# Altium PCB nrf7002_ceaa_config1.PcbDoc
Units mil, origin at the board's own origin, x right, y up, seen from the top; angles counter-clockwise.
Board outline 582.35 x 436 mil, 4 copper layers (Top Layer, Mid-Layer 1, Mid-Layer 2, Bottom Layer), stack 37.194 mil thick; 22 components, 31 nets, 129 pads, 199 vias.
Unrouted connection lines stored in the file: 1.
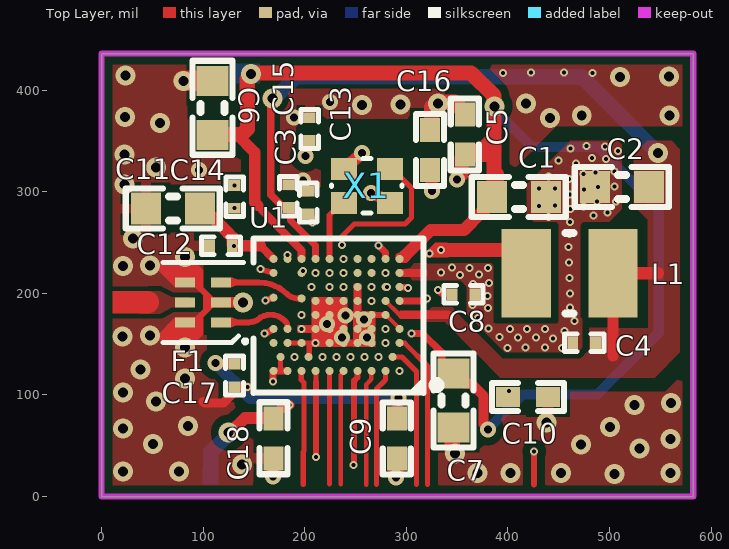
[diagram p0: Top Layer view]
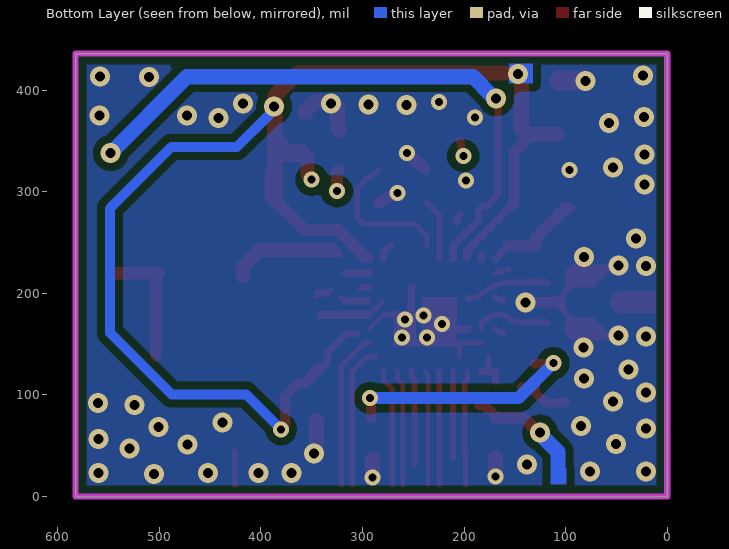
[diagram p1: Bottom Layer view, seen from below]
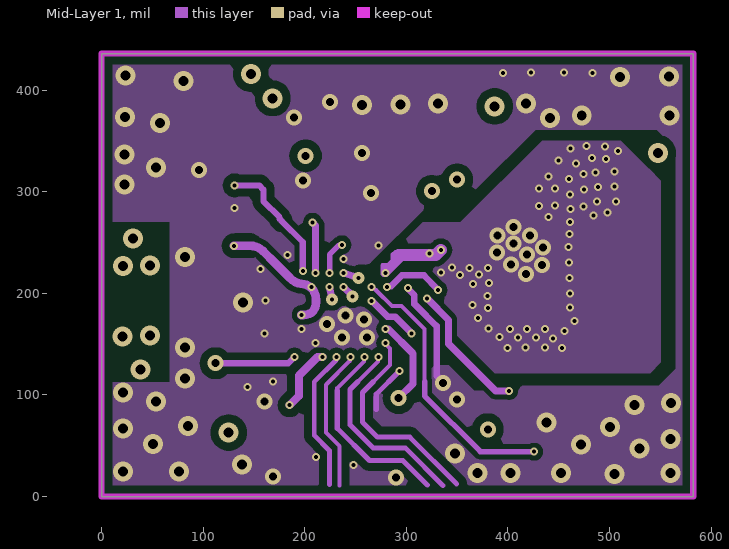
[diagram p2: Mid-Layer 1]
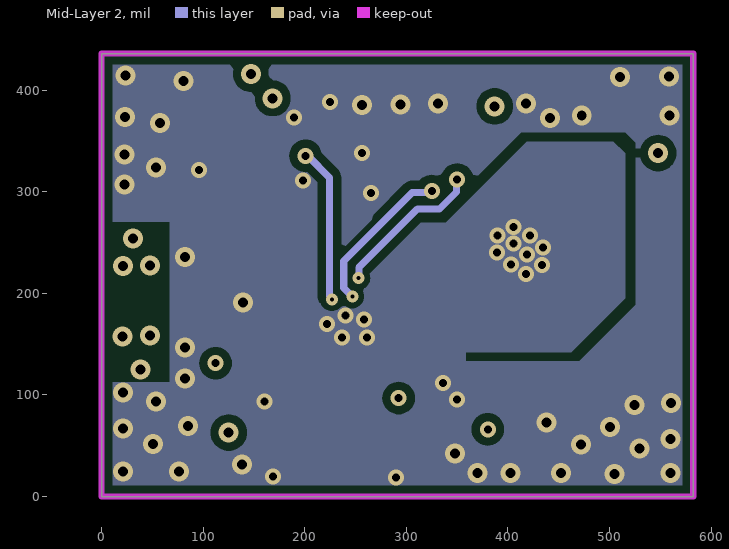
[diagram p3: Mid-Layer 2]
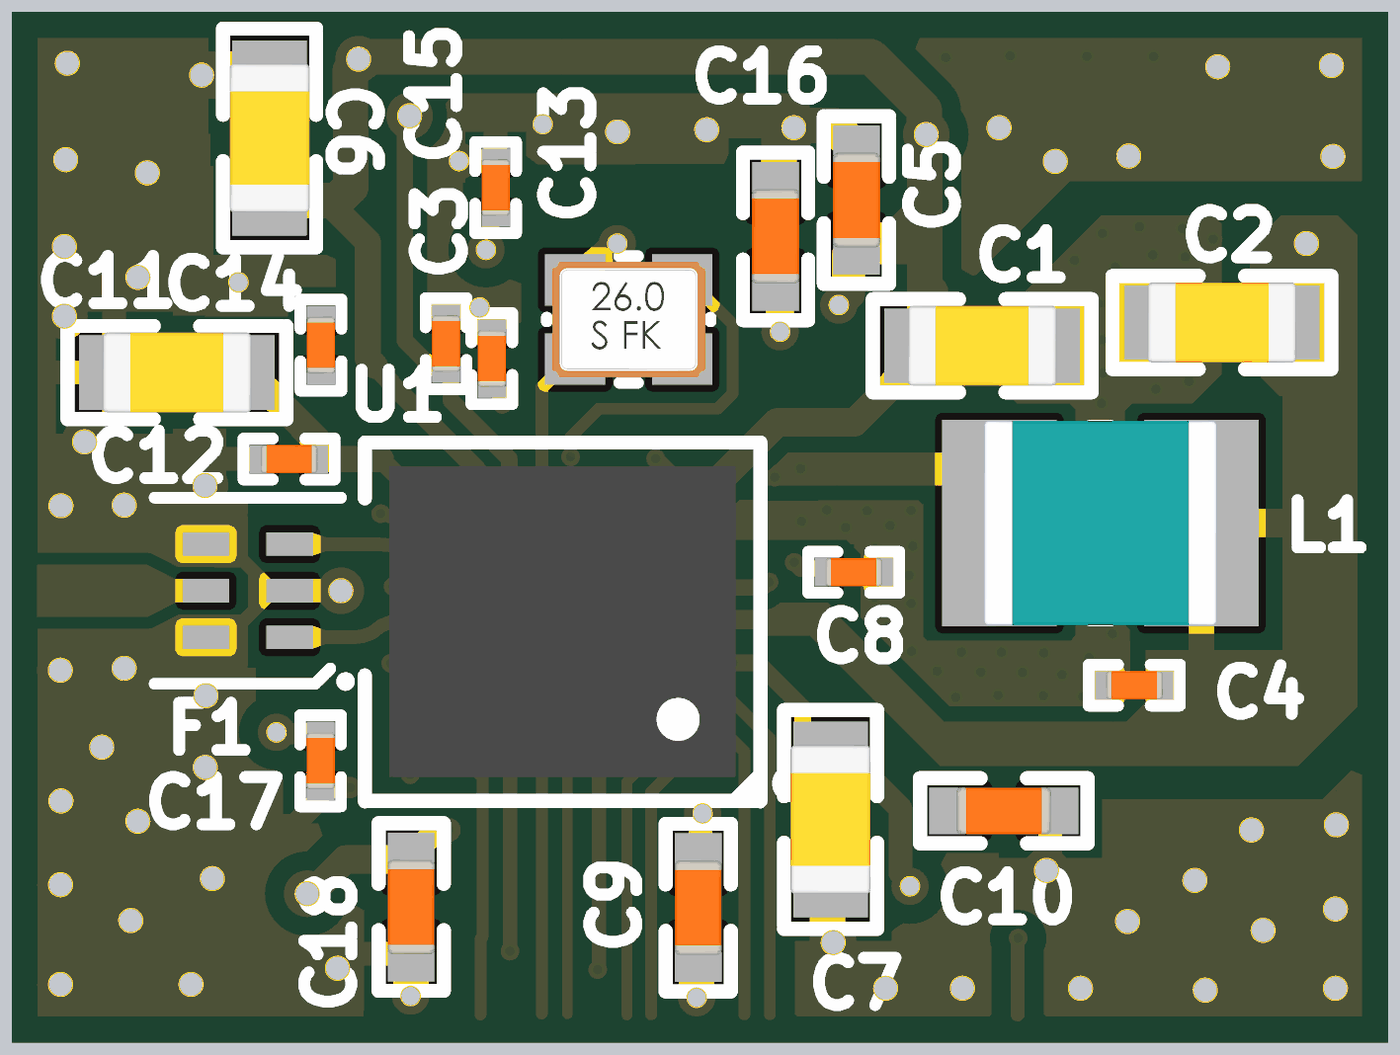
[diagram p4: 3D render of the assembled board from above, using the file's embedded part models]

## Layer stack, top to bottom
Top Solder: solder mask 1.063, Solder Resist, Dk 3.5
Top Layer: signal copper 0.709
Dielectric1: prepreg 3.5, FR-4, Dk 4.2
Mid-Layer 1: signal copper 1.378
Dielectric2: prepreg 26.02, FR-4, Dk 4.2
Mid-Layer 2: signal copper 1.378
Dielectric3: prepreg 3.5, FR-4, Dk 4.2
Bottom Layer: signal copper 0.709
Bottom Solder: solder mask 1.063, Solder Resist, Dk 3.5

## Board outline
0,0 0,436 582.35,436 582.35,0

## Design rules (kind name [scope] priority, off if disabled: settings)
Clearance Clearance_1 [InNet('RF_COM') vs InNet('GND')] p1: gap=4.76 ignorepadtopadclearanceinfootprint=TRUE except(5: Arc-Arc Arc-Track Arc-Fill Arc-Poly Arc-Region Track-Track Track-Fill Track-Poly Track-Region SMDPad-Fill SMDPad-Poly SMDPad-Region Fill-Fill Fill-Poly Fill-Region Poly-Poly Poly-Region Region-Region)
Clearance ANT_Clerance [InNamedPolygon('Top_Layer-GND') vs InNet('RF')] p2: gap=5 ignorepadtopadclearanceinfootprint=FALSE except(0: Arc-Hole Track-Hole SMDPad-Hole THPad-Hole Via-Hole Fill-Hole Poly-Hole Region-Hole Text-Hole)
Clearance Clearance_5 [InNet('BUCKEN') or InNet('DIGVDD') vs OnLayer('Mid-Layer 1')] p3: gap=5 ignorepadtopadclearanceinfootprint=FALSE
Clearance Clearance_2 [InNet('VDD_BUCK') vs OnLayer('Top Layer')] p4: gap=6 ignorepadtopadclearanceinfootprint=FALSE except(3.7: Arc-SMDPad Track-SMDPad; 5: Arc-Arc Arc-Track Track-Track; 5.5: SMDPad-SMDPad)
Clearance Clearance_bga [WithinRoom('bga')] p5: gap=5.5 ignorepadtopadclearanceinfootprint=FALSE except(4: Arc-Arc Arc-Track Arc-SMDPad Arc-THPad Arc-Via Track-Track Track-SMDPad Track-THPad Track-Via SMDPad-SMDPad SMDPad-THPad SMDPad-Via THPad-THPad THPad-Via Via-Via; 4.3: Arc-Text Track-Text SMDPad-Text THPad-Text Via-Text Fill-Text Poly-Text Region-Text Text-Text; 5: Arc-Hole Track-Hole SMDPad-Hole THPad-Hole Via-Hole Fill-Hole Poly-Hole Region-Hole Text-Hole)
Clearance Clearacnce_microvia [AsMM(ViaDiameter) = 0.3 vs AsMM(ViaDiameter) = 0.3] p6: gap=3.94 ignorepadtopadclearanceinfootprint=FALSE
Clearance Polygon_Clearance [(InNamedPolygon('Top_Layer-GND')) or (InNamedPolygon('Bottom_Layer-GND')) or (InNamedPolygon('Mid_Layer_1-GND')) or (InNamedPolygon('Mid_Layer_4-GND'))] p7: gap=8 ignorepadtopadclearanceinfootprint=FALSE except(0: Arc-Hole Track-Hole SMDPad-Hole THPad-Hole Via-Hole Fill-Hole Poly-Hole Region-Hole Text-Hole)
Clearance [All] p8: gap=6 ignorepadtopadclearanceinfootprint=FALSE except(0: Arc-Hole Track-Hole SMDPad-Hole THPad-Hole Via-Hole Fill-Hole Poly-Hole Region-Hole Text-Hole; 5.5: Arc-Arc Arc-Track Track-Track SMDPad-Region; 5.7: THPad-Via)
ComponentClearance [All] p1 off: gap=10 collisioncheckmode=3 verticalgap=10 showdistances=FALSE
DiffPairsRouting [All] p1: maxlimit=8 minlimit=3 mostfreqgap=7.5 toplayer_mingap=5 toplayer_minwidth=4.3 toplayer_maxwidth=4.5 toplayer_prefwidth=4.3 midlayer1_maxgap=4 midlayer1_prefgap=3.5 midlayer1_minwidth=4.3 midlayer1_maxwidth=5 midlayer1_prefwidth=4.3 midlayer4_maxgap=4 midlayer4_prefgap=3.5 midlayer4_minwidth=4.3 midlayer4_maxwidth=5 midlayer4_prefwidth=4.3 bottomlayer_mingap=5 bottomlayer_minwidth=4.3 bottomlayer_maxwidth=4.5 bottomlayer_prefwidth=4.3 maxuncoupledlength=500
FabricationTestPointUsage TestPointUsage [All] p1: valid=0 allowmultiple=FALSE
FabricationTestpoint Testpoint [All] p1: side=3 testpointundercomponent=TRUE minsize=40 maxsize=100 preferedsize=60 minholesize=0 maxholesize=40 preferedholesize=32 testpointgrid=1 allowsidetop=TRUE allowsidebottom=TRUE usegrid=TRUE gridtolerance=0.01
Height [All] p1 off: minheight=0 maxheight=1000 prefheight=500
HoleSize [All] p1: absolutevalues=TRUE maxlimit=300 minlimit=3.94 maxpercent=80.000 minpercent=20.000
HoleToHoleClearance [All] p1: gap=7 allowstackedmicrovias=TRUE
MinimumAnnularRing [All] p1 off: minimumring=6
PolygonConnect PolygonConnect_1 [isVia and innet(gnd) or InComponent('J5_not for this board')] p1: connectstyle=Direct reliefconductorwidth=10 reliefentries=4 polygonreliefangle="90 Angle" airgapwidth=10
PolygonConnect [All] p2: connectstyle=Relief reliefconductorwidth=10 reliefentries=4 polygonreliefangle="90 Angle" airgapwidth=10
RoomDefinition bga [False vs False] p1: confinementstyle=ConfineIn formatcopy=TRUE lockcomponents=FALSE outline 136.29,271.2 341.54,271.2 341.54,113.29 136.29,113.29
RoutingVias [All] p1: holewidth=12.01 width=24 viastyle="Through Hole" minholewidth=3.94 minwidth=11.81 maxholewidth=12.01 maxwidth=24.02 useviatemplates=TRUE viatemplateguid#1={ABC4FB01-9861-4EA0-89FF-0108A0A2DD33} viatemplateguid#2={9F61FF23-C90F-4B7F-A7DC-5F6911D9F630} viatemplateguid#3={EDF5FEF7-A820-4EA2-9A2F-3AF23343353B} viatemplateguid#4={9A17AC30-7ABC-4A8B-B742-8CA8D66FB78C} viatemplateguid#5={FF87C72B-F86E-4E3E-89CE-017383A4E30D} viatemplatename#1=v20h10m0 viatemplatename#2=v40h20m0mx0 viatemplatename#3=v50h25m0mx0 viatemplatename#4=v50h25m0mx0_2670034071 viatemplatename#5=v30h10
SilkToSolderMaskClearance SilkscreenOverComponentPads [IsPad] p1: minsilkscreentomaskgap=10 clearancetoexposedcopper=TRUE
SolderMaskExpansion [IsVia] p1: expansion=3 istentingtop=TRUE
SolderMaskExpansion SolderMaskExpansion_1 [All] p2: expansion=3 istentingtop=FALSE
SupplyNets "Schematic Supply Nets_5" [InNet('GND')] p1: voltage=0.000
SupplyNets "Schematic Supply Nets_4" [InNet('PWRIOVDD')] p2: voltage=0.000
SupplyNets "Schematic Supply Nets_3" [InNet('VDDIO')] p3: voltage=0.000
SupplyNets "Schematic Supply Nets_2" [InNet('VDD_BUCK')] p4: voltage=0.000
SupplyNets "Schematic Supply Nets_1" [InNet('PALDO')] p5: voltage=0.000
SupplyNets "Schematic Supply Nets" [InNet('VBAT')] p6: voltage=0.000
UnRoutedNet [All] p1: checkbadconnections=TRUE
Width [All] p1: maxlimit=50 minlimit=4 preferedwidth=6
21 further rules are at their usual default settings.

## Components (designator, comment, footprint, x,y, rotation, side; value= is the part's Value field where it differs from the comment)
C1 "4.7µF" CAPC1608X06L 410.63,294.77 r180 top
C2 "4.7µF" CAPC1608X06L 512,304.6 r0 top
C3 "0.22µF" CAPC0603X03L_C 183.88,295.65 r270 top
C4 "0.47µF" CAPC0603X03L_C 474.97,151.19 r0 top
C5 "1.0µF" CAPC1005X04L 357.46,356.4 r270 top
C6 "4.7µF" CAPC1608X06L 109.25,382.66 r270 top
C7 "2.2µF" CAPC1608X06L 346.51,94.38 r90 top
C8 "10nF" CAPC0603X03L_C 356.32,198.96 r180 top
C9 "2.2µF" CAPC1005X04L 290.53,57.09 r90 top
C10 "1.0µF" CAPC1005X04L 419.76,98.05 r0 top
C11 "4.7µF" CAPC1608X06L 70.08,283.43 r0 top
C12 "100nF" CAPC0603X03L_C 117.47,246.85 r0 top
C13 "22nF" CAPC0603X03L_C 203.26,289.32 r270 top
C14 "0.47µF" CAPC0603X03L_C 130.98,295.06 r90 top
C15 "2.2µF" CAPC0603X03L_C 204.85,361.7 r270 top
C16 "1.0µF" CAPC1005X04L 323.26,341.03 r270 top
C17 "100nF" CAPC0603X03L_C 130.79,119.2 r90 top
C18 "2.2µF" CAPC1005X04L 169.14,57.37 r90 top
F1 "LFD_5G_Diplexer" CAF-50P160X80-6N 100.03,191.15 r180 top value=LFD182G45DCHD277
L1 "3.3µH" INDC2520X10N 460.62,219.77 r0 top
U1 "nRF7002-CEAA" nRF7002_WLCSP_R2 233.2,179.61 r180 top
X1 "40MHz" BT-XTAL_1612 261.11,305.87 r0 top locked

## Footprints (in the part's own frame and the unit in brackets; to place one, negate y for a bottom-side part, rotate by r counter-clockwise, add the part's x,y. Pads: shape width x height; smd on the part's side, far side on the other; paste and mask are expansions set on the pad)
BT-XTAL_1612 [mm] "Crystal 1.6 x 1.2 mm"
  rect 0.65x0.55 smd: 1(-0.575,-0.425) 2(0.575,-0.425) 3(0.575,0.425) 4(-0.575,0.425)
  silkscreen extent -0.88,-0.68 0.88,0.68, body extent -0.83,-0.63 0.83,0.63, height 0.41
CAF-50P160X80-6N [mm] "Chip Array, Flat, 6-Leads, Pitch 0,50mm,  Body 1,60x0,80mm,  IPC Medium Density"
  rect 0.5x0.25 smd mask+0.08: 1(-0.45,0.5) 2(-0.45,0) 3(-0.45,-0.5) 5(0.45,-0.5) 6(0.45,0) 7(0.45,0.5)
  Top Layer region: 0.693,0.375 0.2,0.375 0,0.175 0,-0.175 0.2,-0.375 0.699,-0.375 1.175,-0.852 1.175,-0.95 0.15,-0.95 0,-0.8 0,-0.375 -0.25,-0.125 -0.8,-0.125 -0.9,-0.225 -1,-0.225 -1,0.225 -0.9,0.225 -0.8,0.125 -0.25,0.125 0,0.375 0,0.8 0.15,0.95 1.175,0.95 1.175,0.857
  silkscreen extent -1.1,-1 1,1.02, body extent -0.5,-0.88 0.5,0.88, height 0.67
CAPC0603X03L_C [mm] "Chip Capacitor, 2-Leads, Body 0.6x0.3mm, IPC High Density"
  rect 0.27x0.3 smd mask+0.05: 1(-0.285,0) 2(0.285,0)
  silkscreen extent -0.49,-0.22 0.49,0.22, body extent -0.3,-0.15 0.31,0.15, height 0.3
CAPC1005X04L [mm] "Chip Capacitor, 2-Leads, Body 1.0x0.5mm, IPC High Density"
  rect 0.6x0.5 smd: 1(-0.5,0) 2(0.5,0)
  silkscreen extent -0.9,-0.35 0.9,0.35, body extent -0.51,-0.25 0.51,0.25, height 0.5
CAPC1608X06L [mm] "Chip Capacitor, 2-Leads, Body 1.6x0.8mm, IPC High Density"
  rect 0.75x0.8 smd: 1(-0.675,0) 2(0.675,0)
  silkscreen extent -1.17,-0.5 1.17,0.5, body extent -0.8,-0.43 0.8,0.43, height 0.8
INDC2520X10N [mm] "Chip Inductor, 2-Leads, Body 2,50x2,00mm, IPC Medium Density"
  rect 1.23x2.22 smd: 1(-1.085,0) 2(1.085,0)
  silkscreen extent -0.1,-1.01 0.1,1.01, body extent -1.25,-1.1 1.25,1.1, height 1.98
nRF7002_WLCSP_R2 [mm] "BGA, 90-Leads, Body 3.72x3.34mmx0.54mm, Pitch 0.34mm"
  round 0.2 smd mask-0.01: A1(-1.526,1.422) A3(-1.176,1.422) A5(-0.826,1.422) A7(-0.476,1.422) A9(-0.126,1.422) A11(0.224,1.422) A13(0.574,1.422) A16(0.924,1.422) A18(1.274,1.422) A20(1.624,1.422) B2(-1.352,1.072) B4(-1.002,1.072) B6(-0.652,1.072) B8(-0.302,1.072) B10(0.049,1.072) B12(0.399,1.072) B15(0.749,1.072) B17(1.099,1.072) B19(1.449,1.072) C1(-1.526,0.722) C3(-1.176,0.722) C5(-0.826,0.722) C7(-0.476,0.722) C9(-0.126,0.722) C11(0.224,0.722) C13(0.574,0.722) C16(0.924,0.722) C18(1.274,0.722) C20(1.624,0.722) D1(-1.526,0.372) D3(-1.176,0.372) D5(-0.826,0.372) D7(-0.476,0.372) D9(-0.126,0.372) D11(0.224,0.372) D13(0.574,0.372) D16(0.924,0.372) D18(1.274,0.372) D20(1.624,0.372) E3(-1.176,0.022) E5(-0.826,0.022) E7(-0.476,0.022) E9(-0.126,0.022) E11(0.224,0.022) E13(0.574,0.022) E16(0.924,0.022) F1(-1.526,-0.328) F3(-1.176,-0.328) F5(-0.826,-0.328) F7(-0.476,-0.328) F9(-0.126,-0.328) F11(0.224,-0.328) F13(0.574,-0.328) G16(0.924,-0.391) H20(1.624,-0.411) J1(-1.526,-0.679) J3(-1.176,-0.679) J5(-0.826,-0.679) J7(-0.476,-0.679) J9(-0.126,-0.679) J11(0.224,-0.679) J14(0.677,-0.679) K1(-1.526,-1.029) K3(-1.176,-1.029) K5(-0.826,-1.029) K7(-0.476,-1.029) K9(-0.126,-1.029) K11(0.224,-1.029) K13(0.574,-1.029) K16(0.924,-1.029) K20(1.624,-1.029) L1(-1.526,-1.379) L3(-1.176,-1.379) L5(-0.826,-1.379) L7(-0.476,-1.379) L9(-0.126,-1.379) L11(0.224,-1.379) L13(0.574,-1.379) L16(0.924,-1.379) L18(1.274,-1.379) L20(1.624,-1.379)
  silkscreen extent -2.53,-1.89 2.13,1.97, body extent -1.86,-1.63 1.86,1.71, height 0.54

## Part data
C1 C2 C6 C11: library part C0603-4µ7-25V-X6S-GRM188C81E475KE11, "Capacitor, Ceramic, X6S 0603,±10%, 25V", Manufacturer=Murata, Manufacturer Part Number=GRM188C81E475KE11D, Supplier Part Number 1=490-7199-1-ND
C3: library part C0201-220n-10V-X5R-GRM033R61A224KE90, "Capacitor, Ceramic, X5R 0201, ±10%, 10V", Manufacturer=Murata, Manufacturer Part Number=GRM033R61A224KE90D, Supplier Part Number 1=81-GRM33R61A224KE90D
C4 C14: library part C0201-470n-6.3V-X5R-GRM033R60J474KE90, "Capacitor, Ceramic, X5R 0201,±10%, 6.3V", Manufacturer=Murata, Manufacturer Part Number=GRM033R60J474KE90D, Supplier Part Number 1=490-10409-1-ND
C5: library part C0402-1µ0-35V-X5R-GRM155R6YA105KE11, "Capacitor, Ceramic, X5R 0402,±10%, 35V", Manufacturer=Murata, Manufacturer Part Number=GRM155R6YA105KE11D, Supplier Part Number 1=81-GRM155R6YA105KE1D
C7: library part C0603-2µ2-16V-X7S-GRM188C71C225KE11, "Capacitor, Ceramic, X7S 0603,±10%,16V", Manufacturer=Murata, Manufacturer Part Number=GRM188C71C225KE11D, Supplier Part Number 1=81-GRM188C71C225KE1D
C8: library part C0201-10n-16V-X7R-GRM033R71C103KE14, "Capacitor, Ceramic, X7R 0201,±10%, 16V", Manufacturer=Murata, Manufacturer Part Number=GRM033R71C103KE14D, Supplier Part Number 1=490-14453-1-ND
C9 C18: library part C0402-2µ2-25V-X5R-GRM155R61E225KE11, "Capacitor, Ceramic, X5R 0402,±10%, 25V", Manufacturer=Murata, Manufacturer Part Number=GRM155R61E225KE11D, Supplier Part Number 1=81-GRM155R61E225KE1D
C10: library part C0402-1µ0-16V-X6S-GRM155C81C105KE11J, "Capacitor, Ceramic, X6S 0402,±10%, 16V", Manufacturer=Murata, Manufacturer Part Number=GRM155C81C105KE11J, Supplier Part Number 1=81-GRM155C81C105KE1J
C12 C17: library part C0201-100n-16V-X7S-GRM033C71C104KE14, "Capacitor, Ceramic, X7S 0201,±10%, 16V", Manufacturer=Murata, Manufacturer Part Number=GRM033C71C104KE14D, Supplier Part Number 1=81-GRM33C71C104KE14D
C13: library part C0201-22n-10V-X5R-GRM033R61A223KE84, "Capacitor, Ceramic, X5R 0201,±10%, 10V", Manufacturer=Murata, Manufacturer Part Number=GRM033R61A223KE84D, Supplier Part Number 1=81-GRM033R61A223KE4E
C15: library part C0201-2µ2-10V-X5R-GRM033R61A225KE47, "Capacitor, Ceramic, X5R 0201,±10%, 10V", Manufacturer=Murata, Manufacturer Part Number=GRM033R61A225KE47D, Supplier Part Number 1=81-GRM033R61A225KE7D
C16: library part C0402-1µ0-10V-X7S-GRM155C71A105KE11, "Capacitor, Ceramic, X7S 0402,±10%,10V", Manufacturer=Murata, Manufacturer Part Number=GRM155C71A105KE11D, Supplier Part Number 1=81-GRM155C71A105KE1J
F1: library part LFD182G45DCHD277, "Signal Conditioning 2.4GHz and 5GHz Diplexer", Manufacturer=Murata, Supplier Part Number 1=81-LFD182G45DCHD277
L1: library part L1008-3µ3-LQM2HPN3R3MGCL, "Inductor, 1A, ±20%, 200mOhm", Manufacturer=Murata, Manufacturer Part Number=LQM2HPN3R3MGCL, Supplier Part Number 1=490-12070-1-ND
U1: "Wi-Fi Dual Band Companion chip WLCSP", Manufacturer="Nordic Semiconductor"
X1: library part XTAL_SMD1612_40MHz_8p_40_85, "XTAL SMD 1612, 40MHz, Cl=8pF, Total Tol: ±10ppm, -40-85C", Manufacturer="Abracon Corporation", Manufacturer Part Number=ABM12W-40.0000MHZ-8-D1X-T3, Supplier Part Number 1=535-13992-1-ND

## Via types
v1: diameter 7.87, hole 3.94, Top Layer to Mid-Layer 1, tented top, 73 vias
v2: diameter 19.68, hole 9.84, Top Layer to Bottom Layer, tented both sides, 52 vias
v3: diameter 7.87, hole 3.94, Top Layer to Mid-Layer 1, tented both sides, 39 vias
v4: diameter 15.75, hole 7.87, Top Layer to Bottom Layer, tented both sides, 19 vias
v5: diameter 15.75, hole 7.87, Mid-Layer 1 to Mid-Layer 2, tented both sides, 13 vias
v6: diameter 11.81, hole 3.94, Mid-Layer 1 to Mid-Layer 2, tented both sides, 3 vias

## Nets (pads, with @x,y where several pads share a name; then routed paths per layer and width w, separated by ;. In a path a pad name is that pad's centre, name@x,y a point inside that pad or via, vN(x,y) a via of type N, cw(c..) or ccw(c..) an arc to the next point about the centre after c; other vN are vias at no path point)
AFELDO: C16.2 U1.J9 | length 185.2
  Top Layer w12: C16.2 325,319.61 325,300.83 v4(325.14,300.69)
  Mid-Layer 1 w7: v3(238.16,206.33) v6@246.73,197.75
  Mid-Layer 2 w7: v6(246.73,196.85) 238.39,205.19 238.39,231.78 277.81,271.2 305.82,299.21 321.66,299.21 v4@323.14,300.69
BUCKEN: U1.J5 | length 298.1
  Top Layer w6: 425.63,12 425.63,44.02 v1(425.83,44.21)
  Mid-Layer 1 w4: v3(265.73,206.33) 266.77,206.33 270.06,203.04 270.35,203.04 285.88,187.51 295.34,187.51 317.91,164.94 317.91,113.29
  Mid-Layer 1 w5.5: 317.91,113.29 317.91,99.14 372.83,44.21 v1(425.83,44.21)
BUCKOUT: L1.1 U1.K3 | length 143.5
  Top Layer w14: v3(333.9,242.73) 401.19,242.73 417.91,226.02 L1.1@417.91,216.77
  Mid-Layer 1 w12: 292.58,237.83 329,237.83 v3(333.9,242.73)
  other v3: 279.56,220.11 322.89,239.15
BUCKVMID: C8.2 U1.J3 | length 74
  Top Layer w7: v1@331.93,202.56 334.07,200.42 341.54,200.42 343.64,200.42 C8.2@344.91,199.15
  Mid-Layer 1 w6.5: v3@281.68,206.61 281.77,206.61 282.2,207.04 284.83,207.04 295.64,217.85 317.56,217.85 ; 317.56,217.29 330.45,204.4 330.9,203.97 v1@331.14,203.97
  other v1: 331.14,203.15
  other v3: 281.14,206.35
COEX_REQ: U1.A5 | length 114.2
  Top Layer w4.5: 260.39,11.68 260.39,110.31 263.37,113.29 265.56,115.47 265.56,123.46 U1.A5
DIGVDD: C10.1 U1.F1 | length 158.9
  Top Layer w7: U1.F1@294.66,192.54 317.95,192.54 320.26,194.86 v3(320.5,194.86)
  Mid-Layer 1 w7: v3(320.5,194.86) 341.54,173.81 341.54,150.38 387.96,103.96 v1(401.19,103.96)
GND: C1.1 C2.1 C3.1 C4.1 C5.1 C6.1 C7.1 C8.1 C9.1 C10.2 C11.1 C12.1 C13.1 C14.1 C15.1 C16.1 C17.1 C18.1 F1.2 F1.5 F1.7 U1.A1 U1.A7 U1.A13 U1.A18 U1.A20 U1.B15 U1.B19 U1.C5 U1.C7 U1.C9 U1.C11 U1.C13 U1.C16 U1.C18 U1.D1 U1.D5 U1.D7 U1.D9 U1.D11 U1.D13 U1.D16 U1.D20 U1.E3 U1.E5 U1.E7 U1.E9 U1.E11 U1.E13 U1.F7 U1.F9 U1.F11 U1.F13 U1.H20 U1.J1 U1.J7 U1.K1 U1.K20 U1.L3 U1.L9 U1.L18 X1.2 X1.4 | length 804.1
  Top Layer w4: U1.L18 U1.L18@183.09,233.96 ; v3(183.15,237.95) v3(183.15,237.95) ; U1.E3 279.78,178.76 293.29,165.25 U1.D1
  Top Layer w5: 175.94,123.63 175.94,137.2 U1.B19 ; U1.C18 U1.C16 204.44,151.19 ; U1.B15@204.44,138.13 204.44,151.19 ; v3(210.59,151.19) 204.44,151.19 ; 210.92,113.29 U1.A13@210.92,123.3
  Top Layer w5.9: v3(156.25,223.75) U1.K20
  Top Layer w6: v2(139.4,191.15) v2@140.17,190.38 ; v1(210.92,38.71) 210.92,113.29 ; v1@248.61,30.88 248.61,114.11 251.89,117.39 251.89,123.57 U1.A7 ; U1.E5 U1.E3@278.27,178.76 ; 316.9,220.11 317.41,220.61
  Top Layer w6.5: U1.C9 U1.C7 ; U1.J1 293.56,206.06 299.9,206.06 301.42,204.54 v3@301.79,204.54
  Top Layer w6.8: v3@161.48,160.43 U1.D20 ; v3(161.48,193.03) U1.H20
  Top Layer w7: v3(168.72,113.29) 168.89,113.46 168.89,123.03 169.34,123.49 169.34,123.63 175.94,123.63 U1.A18 ; U1.L18@183.09,233.96 v3(183.15,237.95) ; U1.E7@251.53,178.35 U1.E7 ; v3(272.52,247.08) 279.4,240.2 279.4,234.24 U1.L3@279.51,234.13
  Top Layer w7.87: U1.K1 316.9,220.11
  Top Layer w8: v4(239.97,178.35) U1.E7@251.53,178.35
  Top Layer w9: 100.03,93.63 101.52,92.14 119.77,92.14 129.89,102.25 129.89,107.66 130.13,107.91 v3(143.39,107.91)
  Top Layer w12: X1.4 v4(256.27,337.96) ; v4@265.28,299.88 X1.2
  Top Layer w15: v4(168.89,19.68) 169.01,19.8 169.01,38.13 C18.1@169.2,38.33 ; v4(289.88,19) C9.1@289.88,37.14 ; C16.1 324.63,362.08 v2@324.63,383.15 ; v2@330.86,386.13 332.12,386.13 334.02,388.03 347.5,388.03 356.32,379.2 C5.1@356.32,377.23 ; C7.1@344.84,74.73 345.24,74.34 345.24,43.07 v2@345.97,42.34
  Top Layer w20: v2(80.51,409.23) C6.1@106.25,409.23
  Mid-Layer 1 w5: 270.35,85.85 270.35,100.68 v3(293.29,123.63)
  Mid-Layer 1 w6.5: v3@301.79,204.54 301.79,204.17 307.88,198.09 307.88,189.47 310.3,187.04 329.15,168.2 329.71,168.2 329.71,119.2 334.8,114.11 v5@334.8,111.61
  other v1: 248.02,30.88 399.37,146.09 453.19,146.39 417.36,146.88 436.5,146.74 444.34,155.68 410,156.7 427.7,156.57 391.59,157.1 455.88,162.85 380.71,165.54 401.84,165.16 418.79,165.16 436.65,164.81 465.68,172.92 370.26,175.81 380.54,185.79 461.02,185.98 365.06,188.31 379.68,197.62 461.13,199.75 365.33,209.11 381.32,210.05 460.59,215.29 352.91,217.88 371.63,218.78 334.24,220.61 344.84,225.32 361.96,225.01 380.54,225.19 459.93,230.56 459.7,245.59 460.59,258.41 461.13,270.44 439.78,275.39 484.09,276.46 498.02,279.67 461.6,283.19 430.66,285.81 446.12,286.64 474.25,285.72 487.55,290.46 506.09,290.35 461.13,297.29 474.97,302.15 430.66,303.38 446.12,303 488.75,304.89 504.96,305.09 459.9,312.6 439.86,315.07 474.47,317.53 486.19,319.06 504.96,319.81 466.96,328.05 449.6,330.93 496.48,332.37 482.69,333.15 508.28,339.88 461.5,342.37 495.28,344.37 477.1,345.12 395.2,416.69 422.44,417.4 454.93,417.2 483.1,417.09
  other v2: 504.96,22.2 369.8,22.99 402.29,22.99 452.2,22.99 559.98,22.99 20.85,24.64 76,24.64 137.98,31.46 347.62,42.34 529.43,47.51 50.55,51.65 472.11,51.25 559.98,56.53 20.85,66.8 500.56,68.63 85.04,69.38 437.82,72.84 524.49,89.95 560.39,92.14 53.55,93.63 21,102.21 82.05,116.44 38.28,124.99 82.34,146.74 20.76,157.54 47.76,158.35 21,227.1 47.76,227.35 81.94,235.66 31,254.12 22.49,307.27 53.55,323.69 22.49,336.72 57.55,367.92 23.02,373.48 441.53,372.75 472.61,375 558.96,374.86 256.46,385.23 294.14,386.13 330.98,387 417.76,387 510.25,412.77 558.3,413.27 23.72,414.27
  other v3: 160.47,160.43 196.81,164.98 301.79,205.31 238.04,233.89 130.98,283.84
  other v4: 236.45,156.68 261.08,156.57 221.94,169.94 258.29,174.4 265.26,298.85 198.04,310.93 96.09,321.6 189.36,372.92 224.79,388.49
  other v5: 160.36,93.77 349.61,95.35 335.8,111.61 417.79,219.07 433.64,227.72 403.04,228.64 418.69,238.32 389.29,240.03 434.64,245.07 405.43,249.02 389.58,257.04 421.44,256.9 405.43,265.49
GRANT: U1.A11 | length 111.3
  Top Layer w5: 224.38,12.31 224.38,113.29 U1.A11
HOST_IRQ: U1.B10 | length 140.7
  Mid-Layer 1 w4.8: 224.32,12 224.32,45.18 209.31,60.19 209.31,112.86 230.74,134.28 230.74,136.86 v3(231.29,137.41)
PALDO: C11.2 C12.2 U1.E16 U1.J14 U1.L20 | length 225.8
  Top Layer w7.87: 156.29,246.85 U1.L20
  Top Layer w11: 123.52,260.3 123.52,260.59 ; C12.2@129.11,247.9 v3(130.25,246.76) ; C12.2@130.25,246.85 156.29,246.85
  Top Layer w12: C11.2 100.67,283.43 123.52,260.59 ; 123.52,260.3 129.11,254.7 C12.2@129.11,247.9
  Mid-Layer 1 w8.5: v3(130.25,246.76) 130.34,246.85 146.32,246.85 cw(c146.32,229.07) 158.89,241.64 170.87,229.65 185.66,214.86 ; 185.66,214.76 ccw(c199.3,228.4) 199.3,209.12 ; v3(196.81,178.76) 198.25,178.76 ccw(c198.25,196.76) 206.92,180.98 ccw(c197.12,190.79) 210.98,190.79 210.98,194.35 ccw(c195.08,194.35) v3@206.32,205.59 ; 199.3,209.02 cw(c195.75,193.51) v3@206.32,205.39
  other v3: 206.55,206.33
PWRIOVDD: C9.2 C17.2 U1.B17 U1.D3 | length 400.7
  Top Layer w9: v4@112.69,130.73 130.48,130.73 C17.2
  Top Layer w10: v4(112.17,131.25) v4@112.69,130.73 ; C9.2 291.45,77.69 291.45,96.04 v4(292.37,96.96)
  Mid-Layer 1 w6: v4(112.17,131.25) 183.77,131.25 v3@189.58,137.05
  Mid-Layer 1 w7: v3(279.51,164.98) 279.68,164.81 282.53,164.81 306.36,140.98 306.36,113.29 306.36,110.94 v4(292.37,96.96)
  Bottom Layer w12: v4(112.17,131.25) 146.46,96.96 v4(292.37,96.96)
  other v3: 189.94,137.41
QSPI_CLK: U1.C1 | length 153.5
  Top Layer w5: U1.C1 293.53,150.95 298.39,150.95 320.84,128.51 320.84,113.29 320.84,12
QSPI_DIO0: U1.B2 | length 140.6
  Top Layer w5: U1.B2 295.69,137.41 310.05,123.05 310.05,12
QSPI_DIO1: U1.B4 | length 194.5
  Mid-Layer 1 w4: 252.49,113.29 272.09,132.89 272.09,136.86 v3(272.64,137.41)
  Mid-Layer 1 w5: 252.49,113.29 244.52,105.32 244.52,70.61 267.19,47.94 298.97,47.94 335.91,11
QSPI_DIO2: U1.A3 | length 115.1
  Top Layer w5: 270.64,12 270.64,106.06 277.87,113.29 279.48,114.9 U1.A3@279.48,123.48
QSPI_DIO3: U1.B6 | length 193.1
  Mid-Layer 1 w4: 231.97,104.38 231.97,106.92 258.11,133.06 258.11,136.67 v3(258.85,137.41)
  Mid-Layer 1 w5: 231.97,104.38 231.97,67.25 263.66,35.57 296.5,35.57 320.65,11.42
QSPI_SS: U1.C3 | length 209
  Mid-Layer 1 w4: 267.67,113.29 283.8,129.42 283.8,145.89 279.32,150.36 v3@279.32,151.19
  Mid-Layer 1 w5: 267.67,113.29 256.75,102.37 256.75,73.23 271.54,58.44 303.32,58.44 349.51,12.25
  other v3: 279.52,151.19
RF_COM: F1.6 | length 22.9
  Top Layer w22: 22.49,191.14 45.41,191.14
RFVDD: C13.2 U1.K13 | length 59.7
  Top Layer w7: C13.2@204.26,277.13 204.85,277.13 206.66,275.31 206.66,270.95 v1(207.66,269.96)
  Mid-Layer 1 w7: v1@207.82,269.79 207.82,269.55 210.55,266.82 v3(210.55,220.19)
STATUS0: U1.B8 | length 142.2
  Mid-Layer 1 w4: 234.22,10.7 234.22,49.53 220.88,62.87 220.88,110.05 244.52,133.69 244.52,136.86 v3(245.07,137.41)
SW_CTRL0: U1.A16 | length 113.3
  Top Layer w5: U1.A16 196.51,123.32 196.51,114.81 198.02,113.29 199.3,112.02 199.3,44.68 198.48,43.86 198.48,11.92
SW_CTRL1: U1.A9 | length 112.6
  Top Layer w4.5: 235.22,12.24 235.22,113.29 235.22,119.91 238.16,122.85 U1.A9
SXLDO: C14.2 U1.K16 | length 124.2
  Mid-Layer 1 w6: v3(130.98,306.29) 155.2,306.29 159.3,302.18 ; 159.3,290.63 175.15,274.77 175.15,273.43 177.39,271.2 198.04,250.54 v3@198.04,224.03 ; 159.4,290.63 159.4,302.18
  other v3: 198.25,222.05
TXRF0: F1.3 U1.G16 | length 83.2
  Top Layer w5.75: F1.3 154.83,210.83 cw(c154.83,174.2) 167.24,208.67 cw(c154.83,174.2) 170.52,207.31 173.92,205.69 cw(c169.24,195.81) 175.95,204.45 ; 175.98,204.43 182.34,199.49 ccw(c193.13,210.27) 185.37,197.15 ccw(c193.13,210.27) 189.73,195.41 ccw(c193.13,210.27) 193.13,195.02 U1.G16
TXRF1: F1.1 U1.D18 | length 146.2
  Top Layer w5.75: 144.81,171.46 ccw(c144.81,188.2) 152.03,173.1 cw(c144.81,188.2) 144.81,171.46 ; 144.81,171.46 F1.1 144.81,171.46 ; 156.49,176.33 cw(c166.42,158.62) 166.46,178.92 ; 156.49,176.33 cw(c166.42,158.62) 166.46,178.92 ; 156.49,176.33 152.64,173.41 156.49,176.33 ; 166.46,178.92 cw(c166.42,159.72) 180,173.29 ; 166.46,178.92 cw(c166.42,159.72) 180,173.29 ; 180,173.29 180.37,172.92 180,173.29 ; 180.39,172.9 cw(c173.39,165.94) 183.26,165.94 ccw(c173.39,165.94) 180.39,172.9
VBAT: C1.2 C5.2 C6.2 C7.2 U1.F5 U1.K9 U1.L1 U1.L16 | length 1742.9
  Top Layer w7: v1(305.11,160.64) 315.8,160.64 334.76,141.67 334.76,131.72 C7.2@341.54,124.94
  Top Layer w7.87: 153.77,286.33 168.08,271.2 ; 169.07,270.21 197.01,242.26 U1.L16@197.01,235.61
  Top Layer w8: C7.2@341.54,124.94 345.53,120.95 C7.2
  Top Layer w10: C7.2@344.51,125.99 348.03,122.47 348.03,120.42 357.26,111.19 363.85,111.19 376.06,98.98 376.06,71.74 380.1,67.7 v4(380.1,66.14)
  Top Layer w11: C6.2@108.65,356.08 C6.2@108.81,356.24 ; 133.32,356.24 150.76,338.81 150.76,293.89 150.76,289.52 153.77,286.33 ; 137.82,356.24 137.98,356.4
  Top Layer w12: 298.3,236.72 323.96,262.38 356.66,262.38 C1.2@373.81,279.52 ; v4(349.97,311.98) 349.97,312.73 349.97,313 353.62,316.65 353.62,332.88 354.12,333.38 C5.2 ; C5.2@359.81,341.03 372.74,341.03 386.32,354.61 386.74,355.02 ; C1.2@383.06,287.79 C1.2@383.06,288.77 ; C1.2@383.06,289.02 386.32,292.29 C1.2@388.82,294.79
  Top Layer w12.5: C1.2@373.79,279.52 C1.2@383.06,287.79
  Top Layer w14: v4@349.97,312.73 354.12,316.88 C5.2@354.12,333.38
  Top Layer w15: C6.2@108.81,356.24 137.82,356.24 ; 137.98,356.4 143.39,361.81 ; 143.59,361.81 143.39,411.22 146.9,414.73 v2(146.9,416) ; v2@146,417 363.62,417 386.08,394.55 v2@386.08,385.02 ; C5.2 372.74,336.72 380.54,336.72 ; 386.32,317.2 386.32,292.29 386.32,336.72 386.32,354.61 v2@386.32,383.47 ; C1.2@388.82,294.79 388.82,317.2
  Mid-Layer 1 w6.8: v3@266,192.54 281.53,177.01 289.01,177.01 295.04,170.98 ; 295.04,170.94 305.11,160.87 v1(305.11,160.64)
  Mid-Layer 1 w7: v3@239.2,219.75 v6(252.83,215.02)
  Mid-Layer 2 w7: v6(252.83,215.02) 253.19,215.38 253.19,225.37 310.78,282.96 332.59,282.96 349.43,299.8 v4@349.43,304.48
  Bottom Layer w10: v4(380.1,66.14) 414.54,100.58 487.92,100.58 548.41,161.07 548.41,283.69 488.1,344 423.68,344 391.82,375.86 391.82,376.66 386.97,381.5 v2(386.97,384.12)
  other v3: 265.73,192.54 238.16,220.11
VDD_BUCK: C2.2 C3.2 C4.2 L1.2 U1.F3 U1.L13 | length 791
  Top Layer w4.2: U1.F3 292.09,179.96 294.14,179.96
  Top Layer w7: v2@168.46,396.77 166.46,394.77 166.46,297.05 178.26,285.25 182.06,285.25 C3.2@183.88,283.43 ; C3.2@185.89,281.7 185.89,271.78 210.59,247.08 U1.L13
  Top Layer w8: 295.16,178.94 341.21,178.94
  Top Layer w10.98: 503.34,138.47 L1.2@503.34,215.52
  Top Layer w12: L1.2@500.56,219.77 L1.2 547.65,219.77
  Bottom Layer w15: v2(168.46,392) 169.73,392 172.07,394.34 172.38,394.34 191.31,413.27 472.5,413.27 v2(547.75,338.02)
VDDIO: C18.2 U1.B12 | length 181.8
  Top Layer w10: C18.2@170.84,80.72 180.07,89.95 v1(185.03,89.95)
  Top Layer w12: v2(125.17,62.99) 126.82,62.99 141.3,77.47 C18.2@168.72,77.47
  Mid-Layer 1 w7.87: v1(185.03,89.95) 194.3,99.22 194.3,119.06 212.58,137.34 v3(217.5,137.34)
  Bottom Layer w15: 107.3,19.9 107.44,20.04 107.44,44 125.17,61.72 v2(125.17,62.99)
XOLDO: C15.2 U1.J11 | length 180
  Top Layer w7.5: v4@200.76,334.55 200.76,336.78 202.69,338.72 202.69,348.91 204.26,350.48 C15.2
  Mid-Layer 1 w7: v3(224.38,206.33) v6(226.58,194.11)
  Mid-Layer 2 w7: v4@203.97,334.38 224.16,314.19 224.16,197.7 226.58,195.28 v6(226.58,194.11)
  other v4: 200.76,335.35
XON: U1.L11 X1.1 | length 60.3
  Top Layer w5.5: U1.L11 224.38,277.01 X1.1@236.51,289.14
XOP: U1.K11 X1.3 | length 177.1
  Top Layer w5: v3(236.53,247.75) 236.53,256.3 248.38,268.15 298.6,268.15 301.65,271.2 305.11,274.66 305.11,303.79 294.62,314.28 292.08,314.28 X1.3
  Mid-Layer 1 w5.5: v3(224.47,220.17) 224.47,238.27 233.69,247.49 236.27,247.49 v3(236.53,247.75)
pads on no net: U1.C20 U1.K5 U1.K7 U1.L5 U1.L7

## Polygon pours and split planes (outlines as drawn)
GND on Top Layer "Top_Layer-GND" (solid, remove dead copper, pour order 53): 0,0 0,436 582.35,436 582.35,0
GND on Top Layer "NONET_L-01_P-001" (solid, pour order 45): 359.2,206.44 352.91,212.73 286.16,212.73 286.16,229.55 383.35,229.55 385.67,227.24 385.67,171.73 387.33,170.07 447.65,170.07 450.79,173.29 450.79,266.95 447.3,270.44 425.32,270.44 417.36,278.39 417.36,306.2 461.06,349.89 508.28,349.89 512.46,345.72 512.46,283.09 499.81,270.44 476.1,270.44 470.98,265.32 470.98,176.92 474.25,173.65 474.25,145.52 469.97,141.35 396.79,141.35 359.2,178.94
VDD_BUCK on Top Layer "NONET_L-01_P-001" (solid, pour order 19): 561,349.96 569.29,341.67 569.29,142.03 544.27,117.01 392.59,117.01 337.53,172.07 319.67,172.07 316.36,175.37 316.36,186.53 344.96,186.63 395.87,135.73 471.36,135.73 479.13,143.5 479.13,262.01 505.14,288.02 505.14,339.67 515.43,349.96
RF_COM on Top Layer "NONET_L-01_P-001" (solid, pour order 54): 57.87,180.15 69.76,186.23 85.71,186.23 85.71,196.07 69.42,196.07 57.55,202.14 36.83,202.14 36.83,180.15
GND on Mid-Layer 1 "Mid_Layer_1-GND" (solid, remove dead copper, pour order 41): 0,0 0,436 582.35,436 582.35,0
GND on Mid-Layer 1 "GND_L02_P049" (solid, pour order 49): 339.23,228.94 339.39,168.16 386.19,121.35 539.36,121.35 550.51,132.49 550.51,310.77 510.93,350.35 433.64,350.35 339.23,255.94
GND on Mid-Layer 2 "Mid_Layer_4-GND" (solid, remove dead copper, pour order 43): 0,0 0,436 582.35,436 582.35,0
GND on Bottom Layer "Bottom_Layer-GND" (solid, remove dead copper, pour order 6): 0,0 0,436 582.35,436 582.35,0

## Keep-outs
Keep-Out Layer:
  the board outline again, w6

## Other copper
Top Layer:
  rectangle net RF_COM: 10.94,180.14 25.03,202.14
  rectangle net GND: 248.16,175.81 255.75,209.67
  rectangle net GND: 206.76,147.45 242.1,196.35
  rectangle net GND: 193.07,161.18 211.92,168.75
  rectangle net GND: 247.43,147.45 269.42,182.55
  pour cut-out: 308.79,230.42 304.55,226.18 cw(c299.7,231.03) 299.7,224.17 297.23,224.17 297.09,224.31 297.09,226.02 298.8,226.02 ccw(c298.8,238.41) 308.36,230.52
  pour cut-out: 178.51,301.56 189.78,301.56 cw(c189.78,298.58) 191.89,300.68 197.35,295.22 209.16,295.22 209.16,283.41 197.35,283.41 178.51,283.43
  pour cut-out: 131.52,394.47 131.52,370.85 84.29,370.85 84.29,394.47
  pour cut-out: 209,34.8 209.43,35.23 212.92,35.23 212.92,7.5 208.74,7.5 208.95,7.71 208.95,35.23
  pour cut-out: 220.82,371.34 220.82,275.63 301.52,275.63 301.52,371.75
  pour cut-out: 502.45,363.28 537.13,363.28 543.69,356.72 519.09,332.12 516.16,332.12 516.16,343.95 502.45,358.68
  pour cut-out: 521.35,288.63 537.51,272.47 511.46,272.47 511.46,278.74
  pour cut-out: 58.27,307.48 81.89,307.48 81.89,259.68 58.27,259.68
  pour cut-out: 359.2,191.87 346.45,191.87 346.45,184.01 394.73,135.73 471.36,135.73 479.82,144.19 479.82,262.98 480.83,263.99 505.9,263.86 523.81,281.76 523.81,345.89 505.42,364.28 447.61,364.28 398.82,315.49 398.82,298.12 355.41,254.7 342.57,254.7 341.79,253.92 341.79,252.18 342.7,251.27 388.72,251.27 409.15,251.27 419.32,261.44 425.8,261.44 425.8,269.96 418.44,277.32 418.44,307.27 461.13,349.96 508.21,349.96 512,346.18 512,282.63 499.81,270.44 474.24,270.44 470.98,267.18 470.98,176.92 473.27,174.63 473.27,146.65 468.87,142.24 396.65,142.24 359.2,179.69
  pour cut-out: 209.16,301.94 209.16,295.22 212.19,295.22 211.92,295.49 211.92,301.94
  pour cut-out: 103.47,158.37 106.32,161.34 161.99,161.34 168.46,154.87 168.46,132.41 196.91,103.96 196.91,75.36 151.25,75.36 103.47,123.14
  region net VBAT: 291.14,239.54 289.46,237.86 289.46,232.16 291.5,230.12 300.14,230.12 303.61,233.59 295.15,242.05 292.65,239.54
  pour cut-out: 561,349.96 569.29,341.67 569.29,142.13 544.24,117.08 392.66,117.08 392.59,117.01 337.53,172.07 313.32,172.07 309.32,168.07 311.28,166.11 311.28,159.59 334.94,159.59 391.48,103.05 554.58,103.05 582.35,130.82 582.35,356.97 575.04,364.28 503.34,364.28 503.34,349.96
  pour cut-out: 130.98,198.96 156.76,198.96 156.76,189.2 147.88,180.32 130.79,180.32
  region net BUCKOUT: 328.35,249.73 340.46,249.73 342.83,247.36 342.83,237.4 341.16,235.73 319.53,235.73 319.26,236 319.26,240.66
  pour cut-out: 100.51,231.22 100.03,230.74 100.03,221.29 157.36,221.29 157.36,231.49 100.46,231.49
  pour cut-out: 249.16,247.75 263.17,261.76 306.5,261.76 307.12,262.38 309.32,260.18 281.21,232.07 249.16,232.07
  pour cut-out: 354.34,186.23 359.2,191.09 359.2,206.42 352.89,212.77 288.79,212.77 288.79,189.2 290.07,189.2 293.04,186.23
  pour cut-out: 305.71,229.55 305.71,237.64 322.62,254.55 346.36,254.55 348.26,252.66 346.83,251.22 329.03,251.22 322.89,245.08 322.89,229.55
Mid-Layer 1:
  pour cut-out: 265.62,230.98 cw(c259,237.59) 258.98,228.24 256.46,228.24 252.68,228.24 ccw(c252.67,223.04) 249.19,226.91 248.69,226.41 ccw(c255.19,219.93) 246.02,219.88 246.02,213.21 245.99,213.18 268.01,213.18 268.01,222.57 315.88,269.97 353.26,269.97 433.64,350.35 511,350.35 550.51,310.84 550.51,132.04 539.82,121.35 386.85,121.35 323.15,185.05 312.66,174.56 378.09,109.13 548.18,109.13 565,125.96 565,342.73 546.66,361.07 427.19,361.07 348.06,281.95 316.58,281.95
  pour cut-out: -25.3,270.33 67.01,270.29 67.01,112.35 -24.02,112.35
  region net BUCKOUT: 275.89,229.48 281.39,229.48 284.83,232.92 284.83,238.83 288.46,242.46 298.46,242.46 300.88,240.03 300.88,236.01 281.22,216.35 276.66,216.35 274.65,218.36 274.65,228.24
  pour cut-out: 327.75,129.09 325.19,126.53 321.06,126.53 319.93,127.67 319.93,163.77 287.83,195.87 287.83,199.06 287.76,199.35 298.03,209.62 316.38,209.62 319.93,206.07 319.93,187.72 396.48,111.16 396.48,108.23 392.21,103.96 366.98,103.96 341.86,129.09
Mid-Layer 2:
  pour cut-out: 338.73,269.97 418.65,349.89 503.81,349.89 515.8,337.9 515.8,194.97 462.18,141.35 359,141.35 359,133.47 469.95,133.47 525.41,188.94 525.41,348 515.31,358.11 412.93,358.1 333.89,279.06 298.12,279.06 298.12,269.97
  pour cut-out: -25.58,270.35 67.01,270.35 67.01,112.35 -24.58,112.35
Bottom Layer:
  rectangle net VBAT: 132.3,406.53 155.82,426
  rectangle net VDDIO: 99.29,11.88 114.92,28.14

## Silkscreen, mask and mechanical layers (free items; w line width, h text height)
Board Outline:
  the board outline again, w6
Bottom Component Info:
  lines w6: 105.04,-35 97.04,-27 112.95,-27 106.95,-33 105.46,-33 105.46,-13 ; 146.62,447 146.62,467 145.13,467 139.13,461 155.04,461 147.04,469
  text "Feed VBAT" at 79.5,483 h25
  text "Feed IOVDD" at 21.74,-76 h25
Top Assembly:
  lines w4.3: 315.08,253.67 149.31,253.67 149.31,102.88 301.36,102.88 315.61,117.13 315.61,253.13
  text "U1" at 246.33,184.22 h15
  text "A1" at 311.49,133.22 h12 r180
Top Top Impedance Info:
  rectangle: 10.94,180.19 57.55,202.14
  lines w4.3: 33.51,172.22 33.51,136.22 ; 123.51,276.22 124.51,276.22 ; 33.51,136.22 34.51,136.22 40.51,142.22 27.51,142.22 33.51,136.22
  lines w5: 123.51,224.22 123.51,276.22 116.51,269.22 131.51,269.22 124.51,276.22
  lines w5.75: 117.75,210.83 154.83,210.83 cw(c154.83,174.2) 167.24,208.67 cw(c154.83,174.2) 170.52,207.31 173.92,205.69 cw(c169.24,195.81) 175.95,204.45 175.98,204.43 182.34,199.49 ccw(c193.13,210.27) 185.37,197.15 ccw(c193.13,210.27) 189.73,195.41 ccw(c193.13,210.27) 193.13,195.02 196.81,195.02 ; 144.81,171.46 ccw(c144.81,188.2) 152.03,173.1 cw(c144.81,188.2) 144.81,171.46 ; 144.81,171.46 117.75,171.46 144.81,171.46 ; 156.49,176.33 cw(c166.42,158.62) 166.46,178.92 ; 156.49,176.33 cw(c166.42,158.62) 166.46,178.92 ; 156.49,176.33 152.64,173.41 156.49,176.33 ; 166.46,178.92 cw(c166.42,159.72) 180,173.29 ; 166.46,178.92 cw(c166.42,159.72) 180,173.29 ; 180,173.29 180.37,172.92 ; 180,173.29 180.37,172.92 ; 180.37,172.92 cw(c173.39,165.94) 180.39,172.9 ; 180.37,172.92 cw(c173.39,165.94) 180.39,172.9 ; 180.39,172.9 cw(c173.39,165.94) 183.26,165.94 ccw(c173.39,165.94) 180.39,172.9
  lines w22: 25,191.14 45.41,191.14
  text "50 ohm  / Microstrip" at 47.19,249.1 h50
  text "50 ohm  / co-planar" at -135,-54 h50
  text "Note: Total Stackup height is 1mm only." at -166,-178.34 h50

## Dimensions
582.35,0 to 582.35,436 on Dimension
0,0 to 582.35,0 on Dimension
